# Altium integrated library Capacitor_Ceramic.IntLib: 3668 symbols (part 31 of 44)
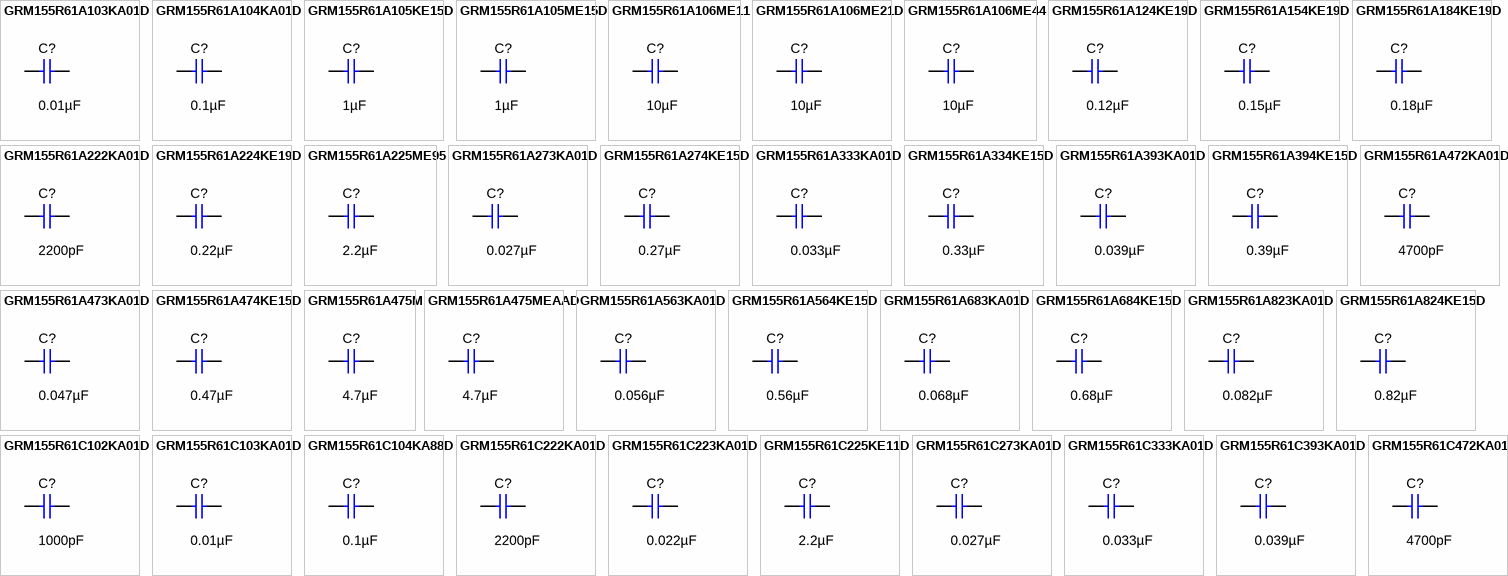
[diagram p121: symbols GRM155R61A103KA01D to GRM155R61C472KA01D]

## GRM155R61A824KE15D
designator C?  ValueDisplayed: 0.82µF  (hidden comment: GRM155R61A824KE15D)
CAP, CERM, 0.82 µF, 10 V,+/- 10%, X5R, 0402; Manufacturer: MuRata; Polarized: N; CompType: Capacitor; Value: 0.82uF; U/M: EA; Cap_F: 0.00000082; Tolerance_%: 10; Value2: 10V; TaMin_C: -55; TaMax_C: 85; Cap_Case: 0402; SizeArea_mm2: 0.5; SizeAreaWB_mm2: 3; SizeX_mm: 1; SizeZ_mm: 0.6; AEC Category: Q200
signal-integrity model Cap
simulation model Cap
footprint 0402
footprint 0402M
footprint 0402L
footprint 0402S
pins: 1, 2

## GRM155R61C102KA01D
designator C?  ValueDisplayed: 1000pF  (hidden comment: GRM155R61C102KA01D)
CAP, CERM, 1000 pF, 16 V,+/- 10%, X5R, 0402; Manufacturer: MuRata; Polarized: N; CompType: Capacitor; Value: 1000pF; U/M: EA; Cap_F: 0.000000001; Tolerance_%: 10; VDC_V: 16; Value2: 16V; TaMin_C: -55; TaMax_C: 85; Cap_Case: 0402; SizeArea_mm2: 0.5; SizeAreaWB_mm2: 3; SizeX_mm: 1; SizeZ_mm: 0.6; AEC Category: Q200
signal-integrity model Cap
simulation model Cap
footprint 0402
footprint 0402M
footprint 0402L
footprint 0402S
pins: 1, 2

## GRM155R61C103KA01D
designator C?  ValueDisplayed: 0.01µF  (hidden comment: GRM155R61C103KA01D)
CAP, CERM, 0.01 µF, 16 V,+/- 10%, X5R, 0402; Manufacturer: MuRata; Polarized: N; CompType: Capacitor; Value: 0.01uF; U/M: EA; Cap_F: 0.00000001; Tolerance_%: 10; VDC_V: 16; Value2: 16V; TaMin_C: -55; TaMax_C: 85; Cap_Case: 0402; SizeArea_mm2: 0.5; SizeAreaWB_mm2: 3; SizeX_mm: 1; SizeZ_mm: 0.6; AEC Category: Q200
signal-integrity model Cap
simulation model Cap
footprint 0402
footprint 0402M
footprint 0402L
footprint 0402S
pins: 1, 2

## GRM155R61C104KA88D
designator C?  ValueDisplayed: 0.1µF  (hidden comment: GRM155R61C104KA88D)
CAP, CERM, 0.1 µF, 16 V,+/- 10%, X5R, 0402; Manufacturer: MuRata; Polarized: N; CompType: Capacitor; Value: 0.1uF; U/M: EA; Cap_F: 0.0000001; Tolerance_%: 10; VDC_V: 16; Value2: 16V; TaMin_C: -55; TaMax_C: 85; Cap_Case: 0402; SizeArea_mm2: 0.5; SizeAreaWB_mm2: 3; SizeX_mm: 1; SizeZ_mm: 0.6; AEC Category: Q200; Green_Lifecycle: Active; Green_REACh: Passed
signal-integrity model Cap
simulation model Cap
footprint 0402
footprint 0402M
footprint 0402L
footprint 0402S
pins: 1, 2

## GRM155R61C222KA01D
designator C?  ValueDisplayed: 2200pF  (hidden comment: GRM155R61C222KA01D)
CAP, CERM, 2200 pF, 16 V,+/- 10%, X5R, 0402; Manufacturer: MuRata; Polarized: N; CompType: Capacitor; Value: 2200pF; U/M: EA; Cap_F: 0.0000000022; Tolerance_%: 10; VDC_V: 16; Value2: 16V; TaMin_C: -55; TaMax_C: 85; Cap_Case: 0402; SizeArea_mm2: 0.5; SizeAreaWB_mm2: 3; SizeX_mm: 1; SizeZ_mm: 0.6; AEC Category: Q200
signal-integrity model Cap
simulation model Cap
footprint 0402
footprint 0402M
footprint 0402L
footprint 0402S
pins: 1, 2

## GRM155R61C223KA01D
designator C?  ValueDisplayed: 0.022µF  (hidden comment: GRM155R61C223KA01D)
CAP, CERM, 0.022 µF, 16 V,+/- 10%, X5R, 0402; Manufacturer: MuRata; Polarized: N; CompType: Capacitor; Value: 0.022uF; U/M: EA; Cap_F: 0.000000022; Tolerance_%: 10; VDC_V: 16; Value2: 16V; TaMin_C: -55; TaMax_C: 85; Cap_Case: 0402; SizeArea_mm2: 0.5; SizeAreaWB_mm2: 3; SizeX_mm: 1; SizeZ_mm: 0.6; AEC Category: Q200; Green_Lifecycle: Active; Green_REACh: Passed
signal-integrity model Cap
simulation model Cap
footprint 0402
footprint 0402M
footprint 0402L
footprint 0402S
pins: 1, 2

## GRM155R61C225KE11D
designator C?  ValueDisplayed: 2.2µF  (hidden comment: GRM155R61C225KE11D)
CAP, CERM, 2.2 µF, 16 V,+/- 10%, X5R, 0402; Manufacturer: MuRata; Polarized: N; CompType: Capacitor; Value: 2.2uF; U/M: EA; Cap_F: 0.0000022; Tolerance_%: 10; VDC_V: 16; Value2: 16V; TaMin_C: -55; TaMax_C: 85; Cap_Case: 0402; SizeArea_mm2: 0.5; SizeAreaWB_mm2: 3; SizeX_mm: 1; SizeZ_mm: 0.6; AEC Category: Q200; Green_Lifecycle: Active; Green_REACh: Passed
signal-integrity model Cap
simulation model Cap
footprint 0402
footprint 0402M
footprint 0402L
footprint 0402S
pins: 1, 2

## GRM155R61C273KA01D
designator C?  ValueDisplayed: 0.027µF  (hidden comment: GRM155R61C273KA01D)
CAP, CERM, 0.027 µF, 16 V,+/- 10%, X5R, 0402; Manufacturer: MuRata; Polarized: N; CompType: Capacitor; Value: 0.027uF; U/M: EA; Cap_F: 0.000000027; Tolerance_%: 10; VDC_V: 16; Value2: 16V; TaMin_C: -55; TaMax_C: 85; Cap_Case: 0402; SizeArea_mm2: 0.5; SizeAreaWB_mm2: 3; SizeX_mm: 1; SizeZ_mm: 0.6; AEC Category: Q200
signal-integrity model Cap
simulation model Cap
footprint 0402
footprint 0402M
footprint 0402L
footprint 0402S
pins: 1, 2

## GRM155R61C333KA01D
designator C?  ValueDisplayed: 0.033µF  (hidden comment: GRM155R61C333KA01D)
CAP, CERM, 0.033 µF, 16 V,+/- 10%, X5R, 0402; Manufacturer: MuRata; Polarized: N; CompType: Capacitor; Value: 0.033uF; U/M: EA; Cap_F: 0.000000033; Tolerance_%: 10; VDC_V: 16; Value2: 16V; TaMin_C: -55; TaMax_C: 85; Cap_Case: 0402; SizeArea_mm2: 0.5; SizeAreaWB_mm2: 3; SizeX_mm: 1; SizeZ_mm: 0.6; AEC Category: Q200; Green_Lifecycle: Active; Green_REACh: Passed
signal-integrity model Cap
simulation model Cap
footprint 0402
footprint 0402M
footprint 0402L
footprint 0402S
pins: 1, 2

## GRM155R61C393KA01D
designator C?  ValueDisplayed: 0.039µF  (hidden comment: GRM155R61C393KA01D)
CAP, CERM, 0.039 µF, 16 V,+/- 10%, X5R, 0402; Manufacturer: MuRata; Polarized: N; CompType: Capacitor; Value: 0.039uF; U/M: EA; Cap_F: 0.000000039; Tolerance_%: 10; VDC_V: 16; Value2: 16V; TaMin_C: -55; TaMax_C: 85; Cap_Case: 0402; SizeArea_mm2: 0.5; SizeAreaWB_mm2: 3; SizeX_mm: 1; SizeZ_mm: 0.6; AEC Category: Q200
signal-integrity model Cap
simulation model Cap
footprint 0402
footprint 0402M
footprint 0402L
footprint 0402S
pins: 1, 2

## GRM155R61C472KA01D
designator C?  ValueDisplayed: 4700pF  (hidden comment: GRM155R61C472KA01D)
CAP, CERM, 4700 pF, 16 V,+/- 10%, X5R, 0402; Manufacturer: MuRata; Polarized: N; CompType: Capacitor; Value: 4700pF; U/M: EA; Cap_F: 0.0000000047; Tolerance_%: 10; VDC_V: 16; Value2: 16V; TaMin_C: -55; TaMax_C: 85; Cap_Case: 0402; SizeArea_mm2: 0.5; SizeAreaWB_mm2: 3; SizeX_mm: 1; SizeZ_mm: 0.6; AEC Category: Q200
signal-integrity model Cap
simulation model Cap
footprint 0402
footprint 0402M
footprint 0402L
footprint 0402S
pins: 1, 2

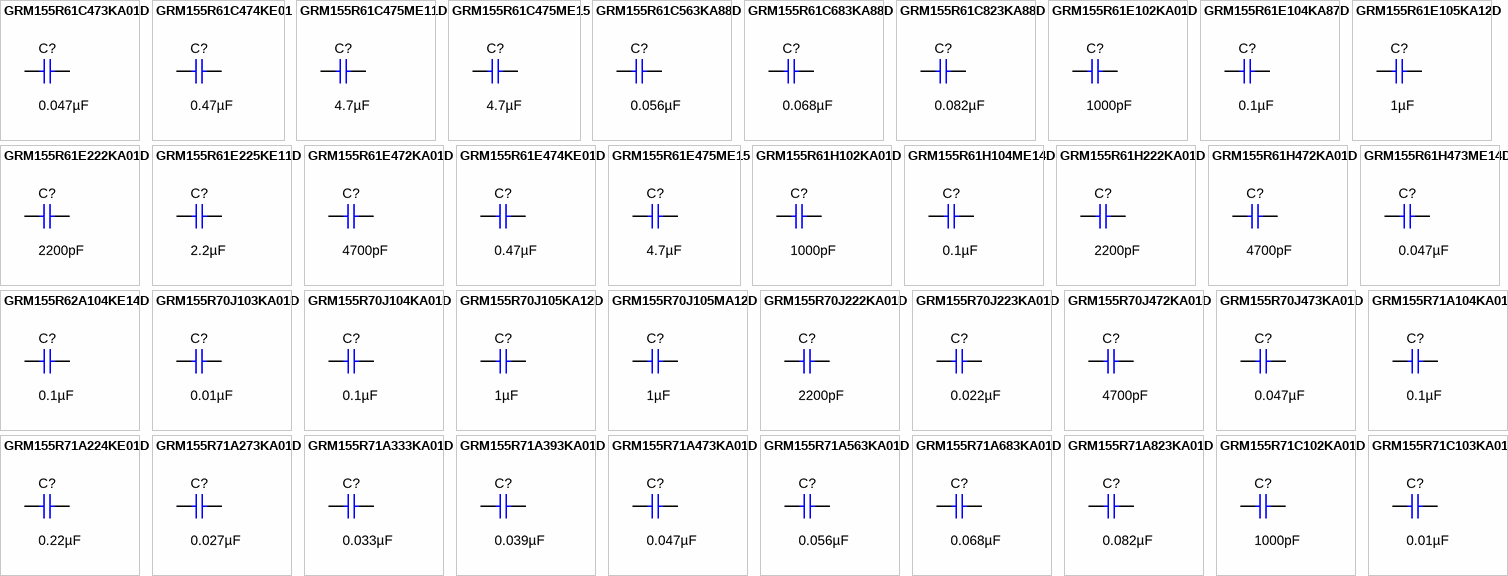
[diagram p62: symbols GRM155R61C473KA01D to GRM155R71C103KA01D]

## GRM155R61C473KA01D
designator C?  ValueDisplayed: 0.047µF  (hidden comment: GRM155R61C473KA01D)
CAP, CERM, 0.047 µF, 16 V,+/- 10%, X5R, 0402; Manufacturer: MuRata; Polarized: N; CompType: Capacitor; Value: 0.047uF; U/M: EA; Cap_F: 0.000000047; Tolerance_%: 10; VDC_V: 16; Value2: 16V; TaMin_C: -55; TaMax_C: 85; Cap_Case: 0402; SizeArea_mm2: 0.5; SizeAreaWB_mm2: 3; SizeX_mm: 1; SizeZ_mm: 0.6; AEC Category: Q200
signal-integrity model Cap
simulation model Cap
footprint 0402
footprint 0402M
footprint 0402L
footprint 0402S
pins: 1, 2

## GRM155R61C474KE01
designator C?  ValueDisplayed: 0.47µF  (hidden comment: GRM155R61C474KE01)
CAP, CERM, 0.47 µF, 16 V,+/- 10%, X5R, 0402; Manufacturer: MuRata; Polarized: N; CompType: Capacitor; Value: 0.47uF; U/M: EA; Cap_F: 0.00000047; Tolerance_%: 10; VDC_V: 16; Value2: 16V; TaMin_C: -55; TaMax_C: 85; Cap_Case: 0402; SizeArea_mm2: 0.5; SizeAreaWB_mm2: 3; SizeX_mm: 1; SizeZ_mm: 0.6; AEC Category: Q200; Green_Lifecycle: Active; Green_REACh: Passed
signal-integrity model Cap
simulation model Cap
footprint 0402
footprint 0402M
footprint 0402L
footprint 0402S
pins: 1, 2

## GRM155R61C475ME11D
designator C?  ValueDisplayed: 4.7µF  (hidden comment: GRM155R61C475ME11D)
CAP, CERM, 4.7 µF, 16 V,+/- 20%, X5R, 0402; Manufacturer: MuRata; Polarized: N; CompType: Capacitor; Value: 4.7uF; U/M: EA; Cap_F: 0.0000047; Tolerance_%: 20; VDC_V: 16; Value2: 16V; TaMin_C: -55; TaMax_C: 85; Cap_Case: 0402; SizeArea_mm2: 0.5; SizeAreaWB_mm2: 3; SizeX_mm: 1; SizeZ_mm: 0.6; AEC Category: Q200; Green_Lifecycle: Not Set; Green_REACh: Incomplete
signal-integrity model Cap
simulation model Cap
footprint 0402
footprint 0402M
footprint 0402L
footprint 0402S
pins: 1, 2

## GRM155R61C475ME15
designator C?  ValueDisplayed: 4.7µF  (hidden comment: GRM155R61C475ME15)
CAP, CERM, 4.7 µF, 16 V,+/- 20%, X5R, 0402; Manufacturer: MuRata; Polarized: N; CompType: Capacitor; Value: 4.7uF; U/M: EA; Cap_F: 0.0000047; Tolerance_%: 20; VDC_V: 16; Value2: 16V; TaMin_C: -55; TaMax_C: 85; Cap_Case: 0402; SizeArea_mm2: 0.5; SizeAreaWB_mm2: 3; SizeX_mm: 1; SizeZ_mm: 0.6; AEC Category: Q200; Green_Lifecycle: Not Set; Green_REACh: Incomplete
signal-integrity model Cap
simulation model Cap
footprint 0402
footprint 0402M
footprint 0402L
footprint 0402S
pins: 1, 2

## GRM155R61C563KA88D
designator C?  ValueDisplayed: 0.056µF  (hidden comment: GRM155R61C563KA88D)
CAP, CERM, 0.056 µF, 16 V,+/- 10%, X5R, 0402; Manufacturer: MuRata; Polarized: N; CompType: Capacitor; Value: 0.056uF; U/M: EA; Cap_F: 0.000000056; Tolerance_%: 10; VDC_V: 16; Value2: 16V; TaMin_C: -55; TaMax_C: 85; Cap_Case: 0402; SizeArea_mm2: 0.5; SizeAreaWB_mm2: 3; SizeX_mm: 1; SizeZ_mm: 0.6; AEC Category: Q200
signal-integrity model Cap
simulation model Cap
footprint 0402
footprint 0402M
footprint 0402L
footprint 0402S
pins: 1, 2

## GRM155R61C683KA88D
designator C?  ValueDisplayed: 0.068µF  (hidden comment: GRM155R61C683KA88D)
CAP, CERM, 0.068 µF, 16 V,+/- 10%, X5R, 0402; Manufacturer: MuRata; Polarized: N; CompType: Capacitor; Value: 0.068uF; U/M: EA; Cap_F: 0.000000068; Tolerance_%: 10; VDC_V: 16; Value2: 16V; TaMin_C: -55; TaMax_C: 85; Cap_Case: 0402; SizeArea_mm2: 0.5; SizeAreaWB_mm2: 3; SizeX_mm: 1; SizeZ_mm: 0.6; AEC Category: Q200
signal-integrity model Cap
simulation model Cap
footprint 0402
footprint 0402M
footprint 0402L
footprint 0402S
pins: 1, 2

## GRM155R61C823KA88D
designator C?  ValueDisplayed: 0.082µF  (hidden comment: GRM155R61C823KA88D)
CAP, CERM, 0.082 µF, 16 V,+/- 10%, X5R, 0402; Manufacturer: MuRata; Polarized: N; CompType: Capacitor; Value: 0.082uF; U/M: EA; Cap_F: 0.000000082; Tolerance_%: 10; VDC_V: 16; Value2: 16V; TaMin_C: -55; TaMax_C: 85; Cap_Case: 0402; SizeArea_mm2: 0.5; SizeAreaWB_mm2: 3; SizeX_mm: 1; SizeZ_mm: 0.6; AEC Category: Q200
signal-integrity model Cap
simulation model Cap
footprint 0402
footprint 0402M
footprint 0402L
footprint 0402S
pins: 1, 2

## GRM155R61E102KA01D
designator C?  ValueDisplayed: 1000pF  (hidden comment: GRM155R61E102KA01D)
CAP, CERM, 1000 pF, 25 V,+/- 10%, X5R, 0402; Manufacturer: MuRata; Polarized: N; CompType: Capacitor; Value: 1000pF; U/M: EA; Cap_F: 0.000000001; Tolerance_%: 10; VDC_V: 25; Value2: 25V; TaMin_C: -55; TaMax_C: 85; Cap_Case: 0402; SizeArea_mm2: 0.5; SizeAreaWB_mm2: 3; SizeX_mm: 1; SizeZ_mm: 0.6; AEC Category: Q200
signal-integrity model Cap
simulation model Cap
footprint 0402
footprint 0402M
footprint 0402L
footprint 0402S
pins: 1, 2

## GRM155R61E104KA87D
designator C?  ValueDisplayed: 0.1µF  (hidden comment: GRM155R61E104KA87D)
CAP, CERM, 0.1 µF, 25 V,+/- 10%, X5R, 0402; Manufacturer: MuRata; Polarized: N; CompType: Capacitor; Value: 0.1uF; U/M: EA; Cap_F: 0.0000001; Tolerance_%: 10; VDC_V: 25; Value2: 25V; TaMin_C: -55; TaMax_C: 85; Cap_Case: 0402; SizeArea_mm2: 0.5; SizeAreaWB_mm2: 3; SizeX_mm: 1; SizeZ_mm: 0.6; AEC Category: Q200; Green_Lifecycle: Active; Green_REACh: Passed
signal-integrity model Cap
simulation model Cap
footprint 0402
footprint 0402M
footprint 0402L
footprint 0402S
pins: 1, 2

## GRM155R61E105KA12D
designator C?  ValueDisplayed: 1µF  (hidden comment: GRM155R61E105KA12D)
CAP, CERM, 1 µF, 25 V,+/- 10%, X5R, 0402; Manufacturer: MuRata; Polarized: N; CompType: Capacitor; Value: 1uF; U/M: EA; Cap_F: 0.000001; Tolerance_%: 10; VDC_V: 25; Value2: 25V; TaMin_C: -55; TaMax_C: 85; Cap_Case: 0402; SizeArea_mm2: 0.5; SizeAreaWB_mm2: 3; SizeX_mm: 1; SizeZ_mm: 0.6; AEC Category: Q200
signal-integrity model Cap
simulation model Cap
footprint 0402
footprint 0402M
footprint 0402L
footprint 0402S
pins: 1, 2

## GRM155R61E222KA01D
designator C?  ValueDisplayed: 2200pF  (hidden comment: GRM155R61E222KA01D)
CAP, CERM, 2200 pF, 25 V,+/- 10%, X5R, 0402; Manufacturer: MuRata; Polarized: N; CompType: Capacitor; Value: 2200pF; U/M: EA; Cap_F: 0.0000000022; Tolerance_%: 10; VDC_V: 25; Value2: 25V; TaMin_C: -55; TaMax_C: 85; Cap_Case: 0402; SizeArea_mm2: 0.5; SizeAreaWB_mm2: 3; SizeX_mm: 1; SizeZ_mm: 0.6; AEC Category: Q200; Green_Lifecycle: Active; Green_REACh: Passed
signal-integrity model Cap
simulation model Cap
footprint 0402
footprint 0402M
footprint 0402L
footprint 0402S
pins: 1, 2

## GRM155R61E225KE11D
designator C?  ValueDisplayed: 2.2µF  (hidden comment: GRM155R61E225KE11D)
CAP, CERM, 2.2 µF, 25 V,+/- 10%, X5R, 0402; Manufacturer: MuRata; Polarized: N; CompType: Capacitor; Value: 2.2uF; U/M: EA; Cap_F: 0.0000022; Tolerance_%: 10; VDC_V: 25; Value2: 25V; TaMin_C: -55; TaMax_C: 85; Cap_Case: 0402; SizeArea_mm2: 0.5; SizeAreaWB_mm2: 3; SizeX_mm: 1; SizeZ_mm: 0.7; AEC Category: Q200; Green_Lifecycle: Active; Green_REACh: Passed
signal-integrity model Cap
simulation model Cap
footprint 0402_070
pins: 1, 2

## GRM155R61E472KA01D
designator C?  ValueDisplayed: 4700pF  (hidden comment: GRM155R61E472KA01D)
CAP, CERM, 4700 pF, 25 V,+/- 10%, X5R, 0402; Manufacturer: MuRata; Polarized: N; CompType: Capacitor; Value: 4700pF; U/M: EA; Cap_F: 0.0000000047; Tolerance_%: 10; VDC_V: 25; Value2: 25V; TaMin_C: -55; TaMax_C: 85; Cap_Case: 0402; SizeArea_mm2: 0.5; SizeAreaWB_mm2: 3; SizeX_mm: 1; SizeZ_mm: 0.6; AEC Category: Q200
signal-integrity model Cap
simulation model Cap
footprint 0402
footprint 0402M
footprint 0402L
footprint 0402S
pins: 1, 2

## GRM155R61E474KE01D
designator C?  ValueDisplayed: 0.47µF  (hidden comment: GRM155R61E474KE01D)
CAP, CERM, 0.47 µF, 25 V,+/- 10%, X5R, 0402; Manufacturer: MuRata; Polarized: N; CompType: Capacitor; Value: 0.47uF; U/M: EA; Cap_F: 0.00000047; Tolerance_%: 10; VDC_V: 25; Value2: 25V; TaMin_C: -55; TaMax_C: 85; Cap_Case: 0402; SizeArea_mm2: 0.5; SizeAreaWB_mm2: 3; SizeX_mm: 1; SizeZ_mm: 0.6; AEC Category: Q200
signal-integrity model Cap
simulation model Cap
footprint 0402
footprint 0402M
footprint 0402L
footprint 0402S
pins: 1, 2

## GRM155R61E475ME15
designator C?  ValueDisplayed: 4.7µF  (hidden comment: GRM155R61E475ME15)
CAP, CERM, 4.7 µF, 25 V,+/- 20%, X5R, 0402; Manufacturer: MuRata; Polarized: N; CompType: Capacitor; Value: 4.7uF; U/M: EA; Cap_F: 0.0000047; Tolerance_%: 20; VDC_V: 25; Value2: 25V; TaMin_C: -55; TaMax_C: 85; Cap_Case: 0402; SizeArea_mm2: 0.5; SizeAreaWB_mm2: 3; SizeX_mm: 1; SizeZ_mm: 0.6; AEC Category: Q200
signal-integrity model Cap
simulation model Cap
footprint 0402
footprint 0402M
footprint 0402L
footprint 0402S
pins: 1, 2

## GRM155R61H102KA01D
designator C?  ValueDisplayed: 1000pF  (hidden comment: GRM155R61H102KA01D)
CAP, CERM, 1000 pF, 50 V,+/- 10%, X5R, 0402; Manufacturer: MuRata; Polarized: N; CompType: Capacitor; Value: 1000pF; U/M: EA; Cap_F: 0.000000001; Tolerance_%: 10; VDC_V: 50; Value2: 50V; TaMin_C: -55; TaMax_C: 85; Cap_Case: 0402; SizeArea_mm2: 0.5; SizeAreaWB_mm2: 3; SizeX_mm: 1; SizeZ_mm: 0.6; AEC Category: Q200
signal-integrity model Cap
simulation model Cap
footprint 0402
footprint 0402M
footprint 0402L
footprint 0402S
pins: 1, 2

## GRM155R61H104ME14D
designator C?  ValueDisplayed: 0.1µF  (hidden comment: GRM155R61H104ME14D)
CAP, CERM, 0.1 µF, 50 V,+/- 20%, X5R, 0402; Manufacturer: MuRata; Polarized: N; CompType: Capacitor; Value: 0.1uF; U/M: EA; Cap_F: 0.0000001; Tolerance_%: 20; VDC_V: 50; Value2: 50V; TaMin_C: -55; TaMax_C: 85; Cap_Case: 0402; SizeArea_mm2: 0.5; SizeAreaWB_mm2: 3; SizeX_mm: 1; SizeZ_mm: 0.6; AEC Category: Q200
signal-integrity model Cap
simulation model Cap
footprint 0402
footprint 0402M
footprint 0402L
footprint 0402S
pins: 1, 2

## GRM155R61H222KA01D
designator C?  ValueDisplayed: 2200pF  (hidden comment: GRM155R61H222KA01D)
CAP, CERM, 2200 pF, 50 V,+/- 10%, X5R, 0402; Manufacturer: MuRata; Polarized: N; CompType: Capacitor; Value: 2200pF; U/M: EA; Cap_F: 0.0000000022; Tolerance_%: 10; VDC_V: 50; Value2: 50V; TaMin_C: -55; TaMax_C: 85; Cap_Case: 0402; SizeArea_mm2: 0.5; SizeAreaWB_mm2: 3; SizeX_mm: 1; SizeZ_mm: 0.6; AEC Category: Q200; Green_Lifecycle: Active; Green_REACh: Passed
signal-integrity model Cap
simulation model Cap
footprint 0402
footprint 0402M
footprint 0402L
footprint 0402S
pins: 1, 2

## GRM155R61H472KA01D
designator C?  ValueDisplayed: 4700pF  (hidden comment: GRM155R61H472KA01D)
CAP, CERM, 4700 pF, 50 V,+/- 10%, X5R, 0402; Manufacturer: MuRata; Polarized: N; CompType: Capacitor; Value: 4700pF; U/M: EA; Cap_F: 0.0000000047; Tolerance_%: 10; VDC_V: 50; Value2: 50V; TaMin_C: -55; TaMax_C: 85; Cap_Case: 0402; SizeArea_mm2: 0.5; SizeAreaWB_mm2: 3; SizeX_mm: 1; SizeZ_mm: 0.6; AEC Category: Q200; Green_Lifecycle: Active; Green_REACh: Passed
signal-integrity model Cap
simulation model Cap
footprint 0402
footprint 0402M
footprint 0402L
footprint 0402S
pins: 1, 2

## GRM155R61H473ME14D
designator C?  ValueDisplayed: 0.047µF  (hidden comment: GRM155R61H473ME14D)
CAP, CERM, 0.047 µF, 50 V,+/- 20%, X5R, 0402; Manufacturer: MuRata; Polarized: N; CompType: Capacitor; Value: 0.047uF; U/M: EA; Cap_F: 0.000000047; Tolerance_%: 20; VDC_V: 50; Value2: 50V; TaMin_C: -55; TaMax_C: 85; Cap_Case: 0402; SizeArea_mm2: 0.5; SizeAreaWB_mm2: 3; SizeX_mm: 1; SizeZ_mm: 0.6; AEC Category: Q200
signal-integrity model Cap
simulation model Cap
footprint 0402
footprint 0402M
footprint 0402L
footprint 0402S
pins: 1, 2

## GRM155R62A104KE14D
designator C?  ValueDisplayed: 0.1µF  (hidden comment: GRM155R62A104KE14D)
CAP, CERM, 0.1 µF, 100 V,+/- 10%, X5R, 0402; Manufacturer: MuRata; Polarized: N; CompType: Capacitor; Value: 0.1uF; U/M: EA; Cap_F: 0.0000001; Tolerance_%: 10; VDC_V: 100; Value2: 100V; TaMin_C: -55; TaMax_C: 85; Cap_Case: 0402; SizeArea_mm2: 0.5; SizeAreaWB_mm2: 3; SizeX_mm: 1; SizeZ_mm: 0.6; AEC Category: Q200
signal-integrity model Cap
simulation model Cap
footprint 0402
footprint 0402M
footprint 0402L
footprint 0402S
pins: 1, 2

## GRM155R70J103KA01D
designator C?  ValueDisplayed: 0.01µF  (hidden comment: GRM155R70J103KA01D)
CAP, CERM, 0.01 µF, 6.3 V,+/- 10%, X7R, 0402; Manufacturer: MuRata; Polarized: N; CompType: Capacitor; Value: 0.01uF; U/M: EA; Cap_F: 0.00000001; Tolerance_%: 10; VDC_V: 6.3; Value2: 6.3V; TaMin_C: -55; TaMax_C: 125; Cap_Case: 0402; SizeArea_mm2: 0.5; SizeAreaWB_mm2: 3; SizeX_mm: 1; SizeZ_mm: 0.6; AEC Category: Q200; Green_Lifecycle: Active; Green_REACh: Passed
signal-integrity model Cap
simulation model Cap
footprint 0402
footprint 0402M
footprint 0402L
footprint 0402S
pins: 1, 2

## GRM155R70J104KA01D
designator C?  ValueDisplayed: 0.1µF  (hidden comment: GRM155R70J104KA01D)
CAP, CERM, 0.1 µF, 6.3 V,+/- 10%, X7R, 0402; Manufacturer: MuRata; Polarized: N; CompType: Capacitor; Value: 0.1uF; U/M: EA; Cap_F: 0.0000001; Tolerance_%: 10; VDC_V: 6.3; Value2: 6.3V; TaMin_C: -55; TaMax_C: 125; Cap_Case: 0402; SizeArea_mm2: 0.5; SizeAreaWB_mm2: 3; SizeX_mm: 1; SizeZ_mm: 0.6; AEC Category: Q200; Green_Lifecycle: Active; Green_REACh: Passed
signal-integrity model Cap
simulation model Cap
footprint 0402
footprint 0402M
footprint 0402L
footprint 0402S
pins: 1, 2

## GRM155R70J105KA12D
designator C?  ValueDisplayed: 1µF  (hidden comment: GRM155R70J105KA12D)
CAP, CERM, 1 µF, 6.3 V,+/- 10%, X7R, 0402; Manufacturer: MuRata; Polarized: N; CompType: Capacitor; Value: 1uF; U/M: EA; Cap_F: 0.000001; Tolerance_%: 10; VDC_V: 6.3; Value2: 6.3V; TaMin_C: -55; TaMax_C: 125; Cap_Case: 0402; SizeArea_mm2: 0.5; SizeAreaWB_mm2: 3; SizeX_mm: 1; SizeZ_mm: 0.6; AEC Category: Q200
signal-integrity model Cap
simulation model Cap
footprint 0402
footprint 0402M
footprint 0402L
footprint 0402S
pins: 1, 2

## GRM155R70J105MA12D
designator C?  ValueDisplayed: 1µF  (hidden comment: GRM155R70J105MA12D)
CAP, CERM, 1 µF, 6.3 V,+/- 20%, X7R, 0402; Manufacturer: MuRata; Polarized: N; CompType: Capacitor; Value: 1uF; U/M: EA; Cap_F: 0.000001; Tolerance_%: 20; VDC_V: 6.3; Value2: 6.3V; TaMin_C: -55; TaMax_C: 125; Cap_Case: 0402; SizeArea_mm2: 0.5; SizeAreaWB_mm2: 3; SizeX_mm: 1; SizeZ_mm: 0.6; AEC Category: Q200
signal-integrity model Cap
simulation model Cap
footprint 0402
footprint 0402M
footprint 0402L
footprint 0402S
pins: 1, 2

## GRM155R70J222KA01D
designator C?  ValueDisplayed: 2200pF  (hidden comment: GRM155R70J222KA01D)
CAP, CERM, 2200 pF, 6.3 V,+/- 10%, X7R, 0402; Manufacturer: MuRata; Polarized: N; CompType: Capacitor; Value: 2200pF; U/M: EA; Cap_F: 0.0000000022; Tolerance_%: 10; VDC_V: 6.3; Value2: 6.3V; TaMin_C: -55; TaMax_C: 125; Cap_Case: 0402; SizeArea_mm2: 0.5; SizeAreaWB_mm2: 3; SizeX_mm: 1; SizeZ_mm: 0.6; AEC Category: Q200
signal-integrity model Cap
simulation model Cap
footprint 0402
footprint 0402M
footprint 0402L
footprint 0402S
pins: 1, 2

## GRM155R70J223KA01D
designator C?  ValueDisplayed: 0.022µF  (hidden comment: GRM155R70J223KA01D)
CAP, CERM, 0.022 µF, 6.3 V,+/- 10%, X7R, 0402; Manufacturer: MuRata; Polarized: N; CompType: Capacitor; Value: 0.022uF; U/M: EA; Cap_F: 0.000000022; Tolerance_%: 10; VDC_V: 6.3; Value2: 6.3V; TaMin_C: -55; TaMax_C: 125; Cap_Case: 0402; SizeArea_mm2: 0.5; SizeAreaWB_mm2: 3; SizeX_mm: 1; SizeZ_mm: 0.6; AEC Category: Q200
signal-integrity model Cap
simulation model Cap
footprint 0402
footprint 0402M
footprint 0402L
footprint 0402S
pins: 1, 2

## GRM155R70J472KA01D
designator C?  ValueDisplayed: 4700pF  (hidden comment: GRM155R70J472KA01D)
CAP, CERM, 4700 pF, 6.3 V,+/- 10%, X7R, 0402; Manufacturer: MuRata; Polarized: N; CompType: Capacitor; Value: 4700pF; U/M: EA; Cap_F: 0.0000000047; Tolerance_%: 10; VDC_V: 6.3; Value2: 6.3V; TaMin_C: -55; TaMax_C: 125; Cap_Case: 0402; SizeArea_mm2: 0.5; SizeAreaWB_mm2: 3; SizeX_mm: 1; SizeZ_mm: 0.6; AEC Category: Q200
signal-integrity model Cap
simulation model Cap
footprint 0402
footprint 0402M
footprint 0402L
footprint 0402S
pins: 1, 2

## GRM155R70J473KA01D
designator C?  ValueDisplayed: 0.047µF  (hidden comment: GRM155R70J473KA01D)
CAP, CERM, 0.047 µF, 6.3 V,+/- 10%, X7R, 0402; Manufacturer: MuRata; Polarized: N; CompType: Capacitor; Value: 0.047uF; U/M: EA; Cap_F: 0.000000047; Tolerance_%: 10; VDC_V: 6.3; Value2: 6.3V; TaMin_C: -55; TaMax_C: 125; Cap_Case: 0402; SizeArea_mm2: 0.5; SizeAreaWB_mm2: 3; SizeX_mm: 1; SizeZ_mm: 0.6; AEC Category: Q200
signal-integrity model Cap
simulation model Cap
footprint 0402
footprint 0402M
footprint 0402L
footprint 0402S
pins: 1, 2

## GRM155R71A104KA01D
designator C?  ValueDisplayed: 0.1µF  (hidden comment: GRM155R71A104KA01D)
CAP, CERM, 0.1 µF, 10 V,+/- 10%, X7R, 0402; Manufacturer: MuRata; Polarized: N; CompType: Capacitor; Value: 0.1uF; U/M: EA; Cap_F: 0.0000001; Tolerance_%: 10; Value2: 10V; TaMin_C: -55; TaMax_C: 125; Cap_Case: 0402; SizeArea_mm2: 0.5; SizeAreaWB_mm2: 3; SizeX_mm: 1; SizeZ_mm: 0.6; AEC Category: Q200; Green_Lifecycle: Active; Green_REACh: Passed
signal-integrity model Cap
simulation model Cap
footprint 0402
footprint 0402M
footprint 0402L
footprint 0402S
pins: 1, 2

## GRM155R71A224KE01D
designator C?  ValueDisplayed: 0.22µF  (hidden comment: GRM155R71A224KE01D)
CAP, CERM, 0.22 µF, 10 V,+/- 10%, X7R, 0402; Manufacturer: MuRata; Polarized: N; CompType: Capacitor; Value: 0.22uF; U/M: EA; Cap_F: 0.00000022; Tolerance_%: 10; Value2: 10V; TaMin_C: -55; TaMax_C: 125; Cap_Case: 0402; SizeArea_mm2: 0.5; SizeAreaWB_mm2: 3; SizeX_mm: 1; SizeZ_mm: 0.6; AEC Category: Q200
signal-integrity model Cap
simulation model Cap
footprint 0402
footprint 0402M
footprint 0402L
footprint 0402S
pins: 1, 2

## GRM155R71A273KA01D
designator C?  ValueDisplayed: 0.027µF  (hidden comment: GRM155R71A273KA01D)
CAP, CERM, 0.027 µF, 10 V,+/- 10%, X7R, 0402; Manufacturer: MuRata; Polarized: N; CompType: Capacitor; Value: 0.027uF; U/M: EA; Cap_F: 0.000000027; Tolerance_%: 10; Value2: 10V; TaMin_C: -55; TaMax_C: 125; Cap_Case: 0402; SizeArea_mm2: 0.5; SizeAreaWB_mm2: 3; SizeX_mm: 1; SizeZ_mm: 0.6; AEC Category: Q200
signal-integrity model Cap
simulation model Cap
footprint 0402
footprint 0402M
footprint 0402L
footprint 0402S
pins: 1, 2

## GRM155R71A333KA01D
designator C?  ValueDisplayed: 0.033µF  (hidden comment: GRM155R71A333KA01D)
CAP, CERM, 0.033 µF, 10 V,+/- 10%, X7R, 0402; Manufacturer: MuRata; Polarized: N; CompType: Capacitor; Value: 0.033uF; U/M: EA; Cap_F: 0.000000033; Tolerance_%: 10; Value2: 10V; TaMin_C: -55; TaMax_C: 125; Cap_Case: 0402; SizeArea_mm2: 0.5; SizeAreaWB_mm2: 3; SizeX_mm: 1; SizeZ_mm: 0.6; AEC Category: Q200; Green_Lifecycle: Active; Green_REACh: Passed
signal-integrity model Cap
simulation model Cap
footprint 0402
footprint 0402M
footprint 0402L
footprint 0402S
pins: 1, 2

## GRM155R71A393KA01D
designator C?  ValueDisplayed: 0.039µF  (hidden comment: GRM155R71A393KA01D)
CAP, CERM, 0.039 µF, 10 V,+/- 10%, X7R, 0402; Manufacturer: MuRata; Polarized: N; CompType: Capacitor; Value: 0.039uF; U/M: EA; Cap_F: 0.000000039; Tolerance_%: 10; Value2: 10V; TaMin_C: -55; TaMax_C: 125; Cap_Case: 0402; SizeArea_mm2: 0.5; SizeAreaWB_mm2: 3; SizeX_mm: 1; SizeZ_mm: 0.6; AEC Category: Q200
signal-integrity model Cap
simulation model Cap
footprint 0402
footprint 0402M
footprint 0402L
footprint 0402S
pins: 1, 2

## GRM155R71A473KA01D
designator C?  ValueDisplayed: 0.047µF  (hidden comment: GRM155R71A473KA01D)
CAP, CERM, 0.047 µF, 10 V,+/- 10%, X7R, 0402; Manufacturer: MuRata; Polarized: N; CompType: Capacitor; Value: 0.047uF; U/M: EA; Cap_F: 0.000000047; Tolerance_%: 10; Value2: 10V; TaMin_C: -55; TaMax_C: 125; Cap_Case: 0402; SizeArea_mm2: 0.5; SizeAreaWB_mm2: 3; SizeX_mm: 1; SizeZ_mm: 0.6; AEC Category: Q200; Green_Lifecycle: Active; Green_REACh: Passed
signal-integrity model Cap
simulation model Cap
footprint 0402
footprint 0402M
footprint 0402L
footprint 0402S
pins: 1, 2

## GRM155R71A563KA01D
designator C?  ValueDisplayed: 0.056µF  (hidden comment: GRM155R71A563KA01D)
CAP, CERM, 0.056 µF, 10 V,+/- 10%, X7R, 0402; Manufacturer: MuRata; Polarized: N; CompType: Capacitor; Value: 0.056uF; U/M: EA; Cap_F: 0.000000056; Tolerance_%: 10; Value2: 10V; TaMin_C: -55; TaMax_C: 125; Cap_Case: 0402; SizeArea_mm2: 0.5; SizeAreaWB_mm2: 3; SizeX_mm: 1; SizeZ_mm: 0.6; AEC Category: Q200
signal-integrity model Cap
simulation model Cap
footprint 0402
footprint 0402M
footprint 0402L
footprint 0402S
pins: 1, 2

## GRM155R71A683KA01D
designator C?  ValueDisplayed: 0.068µF  (hidden comment: GRM155R71A683KA01D)
CAP, CERM, 0.068 µF, 10 V,+/- 10%, X7R, 0402; Manufacturer: MuRata; Polarized: N; CompType: Capacitor; Value: 0.068uF; U/M: EA; Cap_F: 0.000000068; Tolerance_%: 10; Value2: 10V; TaMin_C: -55; TaMax_C: 125; Cap_Case: 0402; SizeArea_mm2: 0.5; SizeAreaWB_mm2: 3; SizeX_mm: 1; SizeZ_mm: 0.6; AEC Category: Q200
signal-integrity model Cap
simulation model Cap
footprint 0402
footprint 0402M
footprint 0402L
footprint 0402S
pins: 1, 2

## GRM155R71A823KA01D
designator C?  ValueDisplayed: 0.082µF  (hidden comment: GRM155R71A823KA01D)
CAP, CERM, 0.082 µF, 10 V,+/- 10%, X7R, 0402; Manufacturer: MuRata; Polarized: N; CompType: Capacitor; Value: 0.082uF; U/M: EA; Cap_F: 0.000000082; Tolerance_%: 10; Value2: 10V; TaMin_C: -55; TaMax_C: 125; Cap_Case: 0402; SizeArea_mm2: 0.5; SizeAreaWB_mm2: 3; SizeX_mm: 1; SizeZ_mm: 0.6; AEC Category: Q200
signal-integrity model Cap
simulation model Cap
footprint 0402
footprint 0402M
footprint 0402L
footprint 0402S
pins: 1, 2

## GRM155R71C102KA01D
designator C?  ValueDisplayed: 1000pF  (hidden comment: GRM155R71C102KA01D)
CAP, CERM, 1000 pF, 16 V,+/- 10%, X7R, 0402; Manufacturer: MuRata; Polarized: N; CompType: Capacitor; Value: 1000pF; U/M: EA; Cap_F: 0.000000001; Tolerance_%: 10; VDC_V: 16; Value2: 16V; TaMin_C: -55; TaMax_C: 125; Cap_Case: 0402; SizeArea_mm2: 0.5; SizeAreaWB_mm2: 3; SizeX_mm: 1; SizeZ_mm: 0.6; AEC Category: Q200; Green_Lifecycle: Active; Green_REACh: Passed
signal-integrity model Cap
simulation model Cap
footprint 0402
footprint 0402M
footprint 0402L
footprint 0402S
pins: 1, 2

## GRM155R71C103KA01D
designator C?  ValueDisplayed: 0.01µF  (hidden comment: GRM155R71C103KA01D)
CAP, CERM, 0.01 µF, 16 V,+/- 10%, X7R, 0402; Manufacturer: MuRata; Polarized: N; CompType: Capacitor; Value: 0.01uF; U/M: EA; Cap_F: 0.00000001; Tolerance_%: 10; VDC_V: 16; Value2: 16V; TaMin_C: -55; TaMax_C: 125; Cap_Case: 0402; SizeArea_mm2: 0.5; SizeAreaWB_mm2: 3; SizeX_mm: 1; SizeZ_mm: 0.6; AEC Category: Q200; Green_Lifecycle: Active; Green_REACh: Passed
signal-integrity model Cap
simulation model Cap
footprint 0402
footprint 0402M
footprint 0402L
footprint 0402S
pins: 1, 2

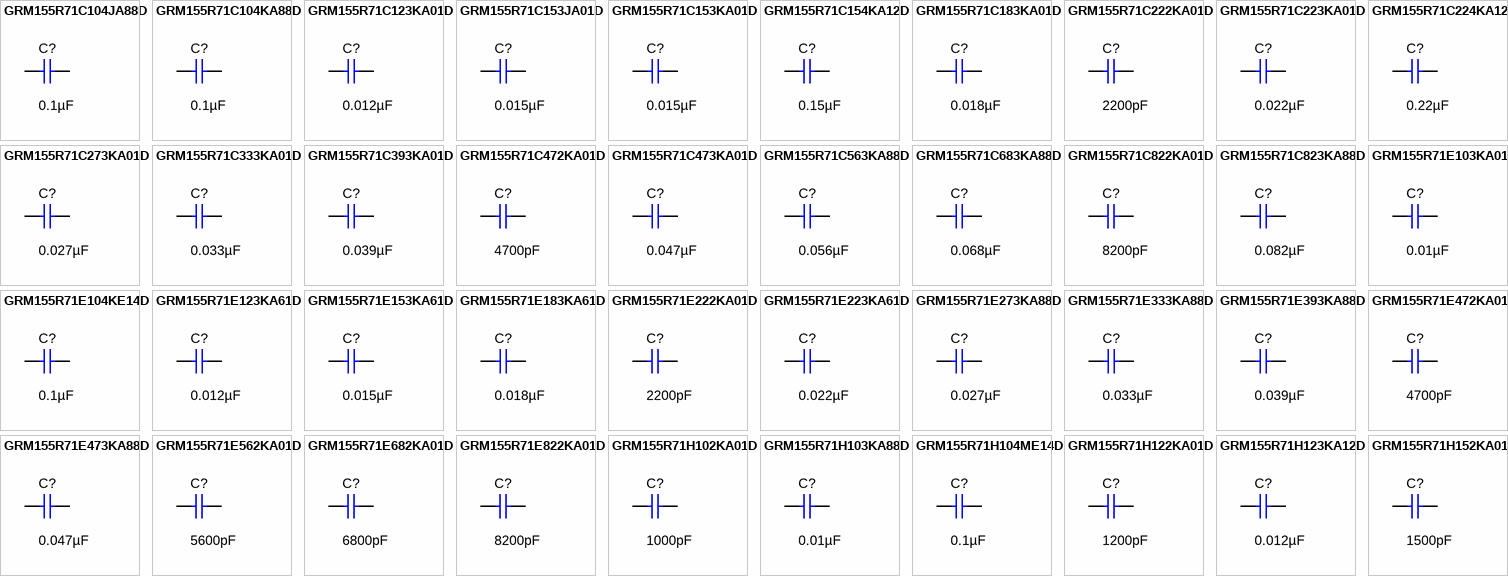
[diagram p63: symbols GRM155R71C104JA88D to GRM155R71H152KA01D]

## GRM155R71C104JA88D
designator C?  ValueDisplayed: 0.1µF  (hidden comment: GRM155R71C104JA88D)
CAP, CERM, 0.1 µF, 16 V,+/- 5%, X7R, 0402; Manufacturer: MuRata; Polarized: N; CompType: Capacitor; Value: 0.1uF; U/M: EA; Cap_F: 0.0000001; Tolerance_%: 5; VDC_V: 16; Value2: 16V; TaMin_C: -55; TaMax_C: 125; Cap_Case: 0402; SizeArea_mm2: 0.5; SizeAreaWB_mm2: 3; SizeX_mm: 1; SizeZ_mm: 0.6; AEC Category: Q200; Green_Lifecycle: Active; Green_REACh: Passed
signal-integrity model Cap
simulation model Cap
footprint 0402
footprint 0402M
footprint 0402L
footprint 0402S
pins: 1, 2

## GRM155R71C104KA88D
designator C?  ValueDisplayed: 0.1µF  (hidden comment: GRM155R71C104KA88D)
CAP, CERM, 0.1 µF, 16 V,+/- 10%, X7R, 0402; Manufacturer: MuRata; Polarized: N; CompType: Capacitor; Value: 0.1uF; U/M: EA; Cap_F: 0.0000001; Tolerance_%: 10; VDC_V: 16; Value2: 16V; TaMin_C: -55; TaMax_C: 125; Cap_Case: 0402; SizeArea_mm2: 0.5; SizeAreaWB_mm2: 3; SizeX_mm: 1; SizeZ_mm: 0.6; AEC Category: Q200; Green_Lifecycle: Active; Green_REACh: Passed
signal-integrity model Cap
simulation model Cap
footprint 0402
footprint 0402M
footprint 0402L
footprint 0402S
pins: 1, 2

## GRM155R71C123KA01D
designator C?  ValueDisplayed: 0.012µF  (hidden comment: GRM155R71C123KA01D)
CAP, CERM, 0.012 µF, 16 V,+/- 10%, X7R, 0402; Manufacturer: MuRata; Polarized: N; CompType: Capacitor; Value: 0.012uF; U/M: EA; Cap_F: 0.000000012; Tolerance_%: 10; VDC_V: 16; Value2: 16V; TaMin_C: -55; TaMax_C: 125; Cap_Case: 0402; SizeArea_mm2: 0.5; SizeAreaWB_mm2: 3; SizeX_mm: 1; SizeZ_mm: 0.6; AEC Category: Q200; Green_Lifecycle: Active; Green_REACh: Passed
signal-integrity model Cap
simulation model Cap
footprint 0402
footprint 0402M
footprint 0402L
footprint 0402S
pins: 1, 2

## GRM155R71C153JA01D
designator C?  ValueDisplayed: 0.015µF  (hidden comment: GRM155R71C153JA01D)
CAP, CERM, 0.015 µF, 16 V,+/- 5%, X7R, 0402; Manufacturer: MuRata; Polarized: N; CompType: Capacitor; Value: 0.015uF; U/M: EA; Cap_F: 0.000000015; Tolerance_%: 5; VDC_V: 16; Value2: 16V; TaMin_C: -55; TaMax_C: 125; Cap_Case: 0402; SizeArea_mm2: 0.5; SizeAreaWB_mm2: 3; SizeX_mm: 1; SizeZ_mm: 0.6; AEC Category: Q200
signal-integrity model Cap
simulation model Cap
footprint 0402
footprint 0402M
footprint 0402L
footprint 0402S
pins: 1, 2

## GRM155R71C153KA01D
designator C?  ValueDisplayed: 0.015µF  (hidden comment: GRM155R71C153KA01D)
CAP, CERM, 0.015 µF, 16 V,+/- 10%, X7R, 0402; Manufacturer: MuRata; Polarized: N; CompType: Capacitor; Value: 0.015uF; U/M: EA; Cap_F: 0.000000015; Tolerance_%: 10; VDC_V: 16; Value2: 16V; TaMin_C: -55; TaMax_C: 125; Cap_Case: 0402; SizeArea_mm2: 0.5; SizeAreaWB_mm2: 3; SizeX_mm: 1; SizeZ_mm: 0.6; AEC Category: Q200; Green_Lifecycle: Active; Green_REACh: Passed
signal-integrity model Cap
simulation model Cap
footprint 0402
footprint 0402M
footprint 0402L
footprint 0402S
pins: 1, 2

## GRM155R71C154KA12D
designator C?  ValueDisplayed: 0.15µF  (hidden comment: GRM155R71C154KA12D)
CAP, CERM, 0.15 µF, 16 V,+/- 10%, X7R, 0402; Manufacturer: MuRata; Polarized: N; CompType: Capacitor; Value: 0.15uF; U/M: EA; Cap_F: 0.00000015; Tolerance_%: 10; VDC_V: 16; Value2: 16V; TaMin_C: -55; TaMax_C: 125; Cap_Case: 0402; SizeArea_mm2: 0.5; SizeAreaWB_mm2: 3; SizeX_mm: 1; SizeZ_mm: 0.6; AEC Category: Q200
signal-integrity model Cap
simulation model Cap
footprint 0402
footprint 0402M
footprint 0402L
footprint 0402S
pins: 1, 2

## GRM155R71C183KA01D
designator C?  ValueDisplayed: 0.018µF  (hidden comment: GRM155R71C183KA01D)
CAP, CERM, 0.018 µF, 16 V,+/- 10%, X7R, 0402; Manufacturer: MuRata; Polarized: N; CompType: Capacitor; Value: 0.018uF; U/M: EA; Cap_F: 0.000000018; Tolerance_%: 10; VDC_V: 16; Value2: 16V; TaMin_C: -55; TaMax_C: 125; Cap_Case: 0402; SizeArea_mm2: 0.5; SizeAreaWB_mm2: 3; SizeX_mm: 1; SizeZ_mm: 0.6; AEC Category: Q200
signal-integrity model Cap
simulation model Cap
footprint 0402
footprint 0402M
footprint 0402L
footprint 0402S
pins: 1, 2

## GRM155R71C222KA01D
designator C?  ValueDisplayed: 2200pF  (hidden comment: GRM155R71C222KA01D)
CAP, CERM, 2200 pF, 16 V,+/- 10%, X7R, 0402; Manufacturer: MuRata; Polarized: N; CompType: Capacitor; Value: 2200pF; U/M: EA; Cap_F: 0.0000000022; Tolerance_%: 10; VDC_V: 16; Value2: 16V; TaMin_C: -55; TaMax_C: 125; Cap_Case: 0402; SizeArea_mm2: 0.5; SizeAreaWB_mm2: 3; SizeX_mm: 1; SizeZ_mm: 0.6; AEC Category: Q200; Green_Lifecycle: Active; Green_REACh: Passed
signal-integrity model Cap
simulation model Cap
footprint 0402
footprint 0402M
footprint 0402L
footprint 0402S
pins: 1, 2

## GRM155R71C223KA01D
designator C?  ValueDisplayed: 0.022µF  (hidden comment: GRM155R71C223KA01D)
CAP, CERM, 0.022 µF, 16 V,+/- 10%, X7R, 0402; Manufacturer: MuRata; Polarized: N; CompType: Capacitor; Value: 0.022uF; U/M: EA; Cap_F: 0.000000022; Tolerance_%: 10; VDC_V: 16; Value2: 16V; TaMin_C: -55; TaMax_C: 125; Cap_Case: 0402; SizeArea_mm2: 0.5; SizeAreaWB_mm2: 3; SizeX_mm: 1; SizeZ_mm: 0.6; AEC Category: Q200; Green_Lifecycle: Active; Green_REACh: Passed
signal-integrity model Cap
simulation model Cap
footprint 0402
footprint 0402M
footprint 0402L
footprint 0402S
pins: 1, 2

## GRM155R71C224KA12D
designator C?  ValueDisplayed: 0.22µF  (hidden comment: GRM155R71C224KA12D)
CAP, CERM, 0.22 µF, 16 V,+/- 10%, X7R, 0402; Manufacturer: MuRata; Polarized: N; CompType: Capacitor; Value: 0.22uF; U/M: EA; Cap_F: 0.00000022; Tolerance_%: 10; VDC_V: 16; Value2: 16V; TaMin_C: -55; TaMax_C: 125; Cap_Case: 0402; SizeArea_mm2: 0.5; SizeAreaWB_mm2: 3; SizeX_mm: 1; SizeZ_mm: 0.6; AEC Category: Q200; Green_Lifecycle: Active; Green_REACh: Passed
signal-integrity model Cap
simulation model Cap
footprint 0402
footprint 0402M
footprint 0402L
footprint 0402S
pins: 1, 2

## GRM155R71C273KA01D
designator C?  ValueDisplayed: 0.027µF  (hidden comment: GRM155R71C273KA01D)
CAP, CERM, 0.027 µF, 16 V,+/- 10%, X7R, 0402; Manufacturer: MuRata; Polarized: N; CompType: Capacitor; Value: 0.027uF; U/M: EA; Cap_F: 0.000000027; Tolerance_%: 10; VDC_V: 16; Value2: 16V; TaMin_C: -55; TaMax_C: 125; Cap_Case: 0402; SizeArea_mm2: 0.5; SizeAreaWB_mm2: 3; SizeX_mm: 1; SizeZ_mm: 0.6; AEC Category: Q200
signal-integrity model Cap
simulation model Cap
footprint 0402
footprint 0402M
footprint 0402L
footprint 0402S
pins: 1, 2

## GRM155R71C333KA01D
designator C?  ValueDisplayed: 0.033µF  (hidden comment: GRM155R71C333KA01D)
CAP, CERM, 0.033 µF, 16 V,+/- 10%, X7R, 0402; Manufacturer: MuRata; Polarized: N; CompType: Capacitor; Value: 0.033uF; U/M: EA; Cap_F: 0.000000033; Tolerance_%: 10; VDC_V: 16; Value2: 16V; TaMin_C: -55; TaMax_C: 125; Cap_Case: 0402; SizeArea_mm2: 0.5; SizeAreaWB_mm2: 3; SizeX_mm: 1; SizeZ_mm: 0.6; AEC Category: Q200
signal-integrity model Cap
simulation model Cap
footprint 0402
footprint 0402M
footprint 0402L
footprint 0402S
pins: 1, 2

## GRM155R71C393KA01D
designator C?  ValueDisplayed: 0.039µF  (hidden comment: GRM155R71C393KA01D)
CAP, CERM, 0.039 µF, 16 V,+/- 10%, X7R, 0402; Manufacturer: MuRata; Polarized: N; CompType: Capacitor; Value: 0.039uF; U/M: EA; Cap_F: 0.000000039; Tolerance_%: 10; VDC_V: 16; Value2: 16V; TaMin_C: -55; TaMax_C: 125; Cap_Case: 0402; SizeArea_mm2: 0.5; SizeAreaWB_mm2: 3; SizeX_mm: 1; SizeZ_mm: 0.6; AEC Category: Q200
signal-integrity model Cap
simulation model Cap
footprint 0402
footprint 0402M
footprint 0402L
footprint 0402S
pins: 1, 2

## GRM155R71C472KA01D
designator C?  ValueDisplayed: 4700pF  (hidden comment: GRM155R71C472KA01D)
CAP, CERM, 4700 pF, 16 V,+/- 10%, X7R, 0402; Manufacturer: MuRata; Polarized: N; CompType: Capacitor; Value: 4700pF; U/M: EA; Cap_F: 0.0000000047; Tolerance_%: 10; VDC_V: 16; Value2: 16V; TaMin_C: -55; TaMax_C: 125; Cap_Case: 0402; SizeArea_mm2: 0.5; SizeAreaWB_mm2: 3; SizeX_mm: 1; SizeZ_mm: 0.6; AEC Category: Q200; Green_Lifecycle: Active; Green_REACh: Passed
signal-integrity model Cap
simulation model Cap
footprint 0402
footprint 0402M
footprint 0402L
footprint 0402S
pins: 1, 2

## GRM155R71C473KA01D
designator C?  ValueDisplayed: 0.047µF  (hidden comment: GRM155R71C473KA01D)
CAP, CERM, 0.047 µF, 16 V,+/- 10%, X7R, 0402; Manufacturer: MuRata; Polarized: N; CompType: Capacitor; Value: 0.047uF; U/M: EA; Cap_F: 0.000000047; Tolerance_%: 10; VDC_V: 16; Value2: 16V; TaMin_C: -55; TaMax_C: 125; Cap_Case: 0402; SizeArea_mm2: 0.5; SizeAreaWB_mm2: 3; SizeX_mm: 1; SizeZ_mm: 0.6; AEC Category: Q200; Green_Lifecycle: Active; Green_REACh: Passed
signal-integrity model Cap
simulation model Cap
footprint 0402
footprint 0402M
footprint 0402L
footprint 0402S
pins: 1, 2

## GRM155R71C563KA88D
designator C?  ValueDisplayed: 0.056µF  (hidden comment: GRM155R71C563KA88D)
CAP, CERM, 0.056 µF, 16 V,+/- 10%, X7R, 0402; Manufacturer: MuRata; Polarized: N; CompType: Capacitor; Value: 0.056uF; U/M: EA; Cap_F: 0.000000056; Tolerance_%: 10; VDC_V: 16; Value2: 16V; TaMin_C: -55; TaMax_C: 125; Cap_Case: 0402; SizeArea_mm2: 0.5; SizeAreaWB_mm2: 3; SizeX_mm: 1; SizeZ_mm: 0.6; AEC Category: Q200
signal-integrity model Cap
simulation model Cap
footprint 0402
footprint 0402M
footprint 0402L
footprint 0402S
pins: 1, 2

## GRM155R71C683KA88D
designator C?  ValueDisplayed: 0.068µF  (hidden comment: GRM155R71C683KA88D)
CAP, CERM, 0.068 µF, 16 V,+/- 10%, X7R, 0402; Manufacturer: MuRata; Polarized: N; CompType: Capacitor; Value: 0.068uF; U/M: EA; Cap_F: 0.000000068; Tolerance_%: 10; VDC_V: 16; Value2: 16V; TaMin_C: -55; TaMax_C: 125; Cap_Case: 0402; SizeArea_mm2: 0.5; SizeAreaWB_mm2: 3; SizeX_mm: 1; SizeZ_mm: 0.6; AEC Category: Q200
signal-integrity model Cap
simulation model Cap
footprint 0402
footprint 0402M
footprint 0402L
footprint 0402S
pins: 1, 2

## GRM155R71C822KA01D
designator C?  ValueDisplayed: 8200pF  (hidden comment: GRM155R71C822KA01D)
CAP, CERM, 8200 pF, 16 V,+/- 10%, X7R, 0402; Manufacturer: MuRata; Polarized: N; CompType: Capacitor; Value: 8200pF; U/M: EA; Cap_F: 0.0000000082; Tolerance_%: 10; VDC_V: 16; Value2: 16V; TaMin_C: -55; TaMax_C: 125; Cap_Case: 0402; SizeArea_mm2: 0.5; SizeAreaWB_mm2: 3; SizeX_mm: 1; SizeZ_mm: 0.6; AEC Category: Q200; Green_Lifecycle: Active; Green_REACh: Passed
signal-integrity model Cap
simulation model Cap
footprint 0402
footprint 0402M
footprint 0402L
footprint 0402S
pins: 1, 2

## GRM155R71C823KA88D
designator C?  ValueDisplayed: 0.082µF  (hidden comment: GRM155R71C823KA88D)
CAP, CERM, 0.082 µF, 16 V,+/- 10%, X7R, 0402; Manufacturer: MuRata; Polarized: N; CompType: Capacitor; Value: 0.082uF; U/M: EA; Cap_F: 0.000000082; Tolerance_%: 10; VDC_V: 16; Value2: 16V; TaMin_C: -55; TaMax_C: 125; Cap_Case: 0402; SizeArea_mm2: 0.5; SizeAreaWB_mm2: 3; SizeX_mm: 1; SizeZ_mm: 0.6; AEC Category: Q200
signal-integrity model Cap
simulation model Cap
footprint 0402
footprint 0402M
footprint 0402L
footprint 0402S
pins: 1, 2

## GRM155R71E103KA01D
designator C?  ValueDisplayed: 0.01µF  (hidden comment: GRM155R71E103KA01D)
CAP, CERM, 0.01 µF, 25 V,+/- 10%, X7R, 0402; Manufacturer: MuRata; Polarized: N; CompType: Capacitor; Value: 0.01uF; U/M: EA; Cap_F: 0.00000001; Tolerance_%: 10; VDC_V: 25; Value2: 25V; TaMin_C: -55; TaMax_C: 125; Cap_Case: 0402; SizeArea_mm2: 0.5; SizeAreaWB_mm2: 3; SizeX_mm: 1; SizeZ_mm: 0.6; AEC Category: Q200; Green_Lifecycle: Active; Green_REACh: Passed
signal-integrity model Cap
simulation model Cap
footprint 0402
footprint 0402M
footprint 0402L
footprint 0402S
pins: 1, 2

## GRM155R71E104KE14D
designator C?  ValueDisplayed: 0.1µF  (hidden comment: GRM155R71E104KE14D)
CAP, CERM, 0.1 µF, 25 V,+/- 10%, X7R, 0402; Manufacturer: MuRata; Polarized: N; CompType: Capacitor; Value: 0.1uF; U/M: EA; Cap_F: 0.0000001; Tolerance_%: 10; VDC_V: 25; Value2: 25V; TaMin_C: -55; TaMax_C: 125; Cap_Case: 0402; SizeArea_mm2: 0.5; SizeAreaWB_mm2: 3; SizeX_mm: 1; SizeZ_mm: 0.6; AEC Category: Q200; Green_Lifecycle: Active; Green_REACh: Passed
signal-integrity model Cap
simulation model Cap
footprint 0402
footprint 0402M
footprint 0402L
footprint 0402S
pins: 1, 2

## GRM155R71E123KA61D
designator C?  ValueDisplayed: 0.012µF  (hidden comment: GRM155R71E123KA61D)
CAP, CERM, 0.012 µF, 25 V,+/- 10%, X7R, 0402; Manufacturer: MuRata; Polarized: N; CompType: Capacitor; Value: 0.012uF; U/M: EA; Cap_F: 0.000000012; Tolerance_%: 10; VDC_V: 25; Value2: 25V; TaMin_C: -55; TaMax_C: 125; Cap_Case: 0402; SizeArea_mm2: 0.5; SizeAreaWB_mm2: 3; SizeX_mm: 1; SizeZ_mm: 0.6; AEC Category: Q200
signal-integrity model Cap
simulation model Cap
footprint 0402
footprint 0402M
footprint 0402L
footprint 0402S
pins: 1, 2

## GRM155R71E153KA61D
designator C?  ValueDisplayed: 0.015µF  (hidden comment: GRM155R71E153KA61D)
CAP, CERM, 0.015 µF, 25 V,+/- 10%, X7R, 0402; Manufacturer: MuRata; Polarized: N; CompType: Capacitor; Value: 0.015uF; U/M: EA; Cap_F: 0.000000015; Tolerance_%: 10; VDC_V: 25; Value2: 25V; TaMin_C: -55; TaMax_C: 125; Cap_Case: 0402; SizeArea_mm2: 0.5; SizeAreaWB_mm2: 3; SizeX_mm: 1; SizeZ_mm: 0.6; AEC Category: Q200
signal-integrity model Cap
simulation model Cap
footprint 0402
footprint 0402M
footprint 0402L
footprint 0402S
pins: 1, 2

## GRM155R71E183KA61D
designator C?  ValueDisplayed: 0.018µF  (hidden comment: GRM155R71E183KA61D)
CAP, CERM, 0.018 µF, 25 V,+/- 10%, X7R, 0402; Manufacturer: MuRata; Polarized: N; CompType: Capacitor; Value: 0.018uF; U/M: EA; Cap_F: 0.000000018; Tolerance_%: 10; VDC_V: 25; Value2: 25V; TaMin_C: -55; TaMax_C: 125; Cap_Case: 0402; SizeArea_mm2: 0.5; SizeAreaWB_mm2: 3; SizeX_mm: 1; SizeZ_mm: 0.6; AEC Category: Q200
signal-integrity model Cap
simulation model Cap
footprint 0402
footprint 0402M
footprint 0402L
footprint 0402S
pins: 1, 2

## GRM155R71E222KA01D
designator C?  ValueDisplayed: 2200pF  (hidden comment: GRM155R71E222KA01D)
CAP, CERM, 2200 pF, 25 V,+/- 10%, X7R, 0402; Manufacturer: MuRata; Polarized: N; CompType: Capacitor; Value: 2200pF; U/M: EA; Cap_F: 0.0000000022; Tolerance_%: 10; VDC_V: 25; Value2: 25V; TaMin_C: -55; TaMax_C: 125; Cap_Case: 0402; SizeArea_mm2: 0.5; SizeAreaWB_mm2: 3; SizeX_mm: 1; SizeZ_mm: 0.6; AEC Category: Q200; Green_Lifecycle: Active; Green_REACh: Passed
signal-integrity model Cap
simulation model Cap
footprint 0402
footprint 0402M
footprint 0402L
footprint 0402S
pins: 1, 2

## GRM155R71E223KA61D
designator C?  ValueDisplayed: 0.022µF  (hidden comment: GRM155R71E223KA61D)
CAP, CERM, 0.022 µF, 25 V,+/- 10%, X7R, 0402; Manufacturer: MuRata; Polarized: N; CompType: Capacitor; Value: 0.022uF; U/M: EA; Cap_F: 0.000000022; Tolerance_%: 10; VDC_V: 25; Value2: 25V; TaMin_C: -55; TaMax_C: 125; Cap_Case: 0402; SizeArea_mm2: 0.5; SizeAreaWB_mm2: 3; SizeX_mm: 1; SizeZ_mm: 0.6; AEC Category: Q200; Green_Lifecycle: Active; Green_REACh: Passed
signal-integrity model Cap
simulation model Cap
footprint 0402
footprint 0402M
footprint 0402L
footprint 0402S
pins: 1, 2

## GRM155R71E273KA88D
designator C?  ValueDisplayed: 0.027µF  (hidden comment: GRM155R71E273KA88D)
CAP, CERM, 0.027 µF, 25 V,+/- 10%, X7R, 0402; Manufacturer: MuRata; Polarized: N; CompType: Capacitor; Value: 0.027uF; U/M: EA; Cap_F: 0.000000027; Tolerance_%: 10; VDC_V: 25; Value2: 25V; TaMin_C: -55; TaMax_C: 125; Cap_Case: 0402; SizeArea_mm2: 0.5; SizeAreaWB_mm2: 3; SizeX_mm: 1; SizeZ_mm: 0.6; AEC Category: Q200; Green_Lifecycle: Active; Green_REACh: Passed
signal-integrity model Cap
simulation model Cap
footprint 0402
footprint 0402M
footprint 0402L
footprint 0402S
pins: 1, 2

## GRM155R71E333KA88D
designator C?  ValueDisplayed: 0.033µF  (hidden comment: GRM155R71E333KA88D)
CAP, CERM, 0.033 µF, 25 V,+/- 10%, X7R, 0402; Manufacturer: MuRata; Polarized: N; CompType: Capacitor; Value: 0.033uF; U/M: EA; Cap_F: 0.000000033; Tolerance_%: 10; VDC_V: 25; Value2: 25V; TaMin_C: -55; TaMax_C: 125; Cap_Case: 0402; SizeArea_mm2: 0.5; SizeAreaWB_mm2: 3; SizeX_mm: 1; SizeZ_mm: 0.6; AEC Category: Q200; Green_Lifecycle: Active; Green_REACh: Passed
signal-integrity model Cap
simulation model Cap
footprint 0402
footprint 0402M
footprint 0402L
footprint 0402S
pins: 1, 2

## GRM155R71E393KA88D
designator C?  ValueDisplayed: 0.039µF  (hidden comment: GRM155R71E393KA88D)
CAP, CERM, 0.039 µF, 25 V,+/- 10%, X7R, 0402; Manufacturer: MuRata; Polarized: N; CompType: Capacitor; Value: 0.039uF; U/M: EA; Cap_F: 0.000000039; Tolerance_%: 10; VDC_V: 25; Value2: 25V; TaMin_C: -55; TaMax_C: 125; Cap_Case: 0402; SizeArea_mm2: 0.5; SizeAreaWB_mm2: 3; SizeX_mm: 1; SizeZ_mm: 0.6; AEC Category: Q200
signal-integrity model Cap
simulation model Cap
footprint 0402
footprint 0402M
footprint 0402L
footprint 0402S
pins: 1, 2

## GRM155R71E472KA01D
designator C?  ValueDisplayed: 4700pF  (hidden comment: GRM155R71E472KA01D)
CAP, CERM, 4700 pF, 25 V,+/- 10%, X7R, 0402; Manufacturer: MuRata; Polarized: N; CompType: Capacitor; Value: 4700pF; U/M: EA; Cap_F: 0.0000000047; Tolerance_%: 10; VDC_V: 25; Value2: 25V; TaMin_C: -55; TaMax_C: 125; Cap_Case: 0402; SizeArea_mm2: 0.5; SizeAreaWB_mm2: 3; SizeX_mm: 1; SizeZ_mm: 0.6; AEC Category: Q200; Green_Lifecycle: Active; Green_REACh: Passed
signal-integrity model Cap
simulation model Cap
footprint 0402
footprint 0402M
footprint 0402L
footprint 0402S
pins: 1, 2

## GRM155R71E473KA88D
designator C?  ValueDisplayed: 0.047µF  (hidden comment: GRM155R71E473KA88D)
CAP, CERM, 0.047 µF, 25 V,+/- 10%, X7R, 0402; Manufacturer: MuRata; Polarized: N; CompType: Capacitor; Value: 0.047uF; U/M: EA; Cap_F: 0.000000047; Tolerance_%: 10; VDC_V: 25; Value2: 25V; TaMin_C: -55; TaMax_C: 125; Cap_Case: 0402; SizeArea_mm2: 0.5; SizeAreaWB_mm2: 3; SizeX_mm: 1; SizeZ_mm: 0.6; AEC Category: Q200; Green_Lifecycle: Active; Green_REACh: Passed
signal-integrity model Cap
simulation model Cap
footprint 0402
footprint 0402M
footprint 0402L
footprint 0402S
pins: 1, 2

## GRM155R71E562KA01D
designator C?  ValueDisplayed: 5600pF  (hidden comment: GRM155R71E562KA01D)
CAP, CERM, 5600 pF, 25 V,+/- 10%, X7R, 0402; Manufacturer: MuRata; Polarized: N; CompType: Capacitor; Value: 5600pF; U/M: EA; Cap_F: 0.0000000056; Tolerance_%: 10; VDC_V: 25; Value2: 25V; TaMin_C: -55; TaMax_C: 125; Cap_Case: 0402; SizeArea_mm2: 0.5; SizeAreaWB_mm2: 3; SizeX_mm: 1; SizeZ_mm: 0.6; AEC Category: Q200
signal-integrity model Cap
simulation model Cap
footprint 0402
footprint 0402M
footprint 0402L
footprint 0402S
pins: 1, 2

## GRM155R71E682KA01D
designator C?  ValueDisplayed: 6800pF  (hidden comment: GRM155R71E682KA01D)
CAP, CERM, 6800 pF, 25 V,+/- 10%, X7R, 0402; Manufacturer: MuRata; Polarized: N; CompType: Capacitor; Value: 6800pF; U/M: EA; Cap_F: 0.0000000068; Tolerance_%: 10; VDC_V: 25; Value2: 25V; TaMin_C: -55; TaMax_C: 125; Cap_Case: 0402; SizeArea_mm2: 0.5; SizeAreaWB_mm2: 3; SizeX_mm: 1; SizeZ_mm: 0.6; AEC Category: Q200; Green_Lifecycle: Active; Green_REACh: Passed
signal-integrity model Cap
simulation model Cap
footprint 0402
footprint 0402M
footprint 0402L
footprint 0402S
pins: 1, 2

## GRM155R71E822KA01D
designator C?  ValueDisplayed: 8200pF  (hidden comment: GRM155R71E822KA01D)
CAP, CERM, 8200 pF, 25 V,+/- 10%, X7R, 0402; Manufacturer: MuRata; Polarized: N; CompType: Capacitor; Value: 8200pF; U/M: EA; Cap_F: 0.0000000082; Tolerance_%: 10; VDC_V: 25; Value2: 25V; TaMin_C: -55; TaMax_C: 125; Cap_Case: 0402; SizeArea_mm2: 0.5; SizeAreaWB_mm2: 3; SizeX_mm: 1; SizeZ_mm: 0.6; AEC Category: Q200
signal-integrity model Cap
simulation model Cap
footprint 0402
footprint 0402M
footprint 0402L
footprint 0402S
pins: 1, 2

## GRM155R71H102KA01D
designator C?  ValueDisplayed: 1000pF  (hidden comment: GRM155R71H102KA01D)
CAP, CERM, 1000 pF, 50 V,+/- 10%, X7R, 0402; Manufacturer: MuRata; Polarized: N; CompType: Capacitor; Value: 1000pF; U/M: EA; Cap_F: 0.000000001; Tolerance_%: 10; VDC_V: 50; Value2: 50V; TaMin_C: -55; TaMax_C: 125; Cap_Case: 0402; SizeArea_mm2: 0.5; SizeAreaWB_mm2: 3; SizeX_mm: 1; SizeZ_mm: 0.6; AEC Category: Q200; Green_Lifecycle: Active; Green_REACh: Passed
signal-integrity model Cap
simulation model Cap
footprint 0402
footprint 0402M
footprint 0402L
footprint 0402S
pins: 1, 2

## GRM155R71H103KA88D
designator C?  ValueDisplayed: 0.01µF  (hidden comment: GRM155R71H103KA88D)
CAP, CERM, 0.01 µF, 50 V,+/- 10%, X7R, 0402; Manufacturer: MuRata; Polarized: N; CompType: Capacitor; Value: 0.01uF; U/M: EA; Cap_F: 0.00000001; Tolerance_%: 10; VDC_V: 50; Value2: 50V; TaMin_C: -55; TaMax_C: 125; Cap_Case: 0402; SizeArea_mm2: 0.5; SizeAreaWB_mm2: 3; SizeX_mm: 1; SizeZ_mm: 0.6; AEC Category: Q200; Green_Lifecycle: Active; Green_REACh: Passed
signal-integrity model Cap
simulation model Cap
footprint 0402
footprint 0402M
footprint 0402L
footprint 0402S
pins: 1, 2

## GRM155R71H104ME14D
designator C?  ValueDisplayed: 0.1µF  (hidden comment: GRM155R71H104ME14D)
CAP, CERM, 0.1 µF, 50 V,+/- 20%, X7R, 0402; Manufacturer: MuRata; Polarized: N; CompType: Capacitor; Value: 0.1uF; U/M: EA; Cap_F: 0.0000001; Tolerance_%: 20; VDC_V: 50; Value2: 50V; TaMin_C: -55; TaMax_C: 125; Cap_Case: 0402; SizeArea_mm2: 0.5; SizeAreaWB_mm2: 3; SizeX_mm: 1; SizeZ_mm: 0.6; AEC Category: Q200
signal-integrity model Cap
simulation model Cap
footprint 0402
footprint 0402M
footprint 0402L
footprint 0402S
pins: 1, 2

## GRM155R71H122KA01D
designator C?  ValueDisplayed: 1200pF  (hidden comment: GRM155R71H122KA01D)
CAP, CERM, 1200 pF, 50 V,+/- 10%, X7R, 0402; Manufacturer: MuRata; Polarized: N; CompType: Capacitor; Value: 1200pF; U/M: EA; Cap_F: 0.0000000012; Tolerance_%: 10; VDC_V: 50; Value2: 50V; TaMin_C: -55; TaMax_C: 125; Cap_Case: 0402; SizeArea_mm2: 0.5; SizeAreaWB_mm2: 3; SizeX_mm: 1; SizeZ_mm: 0.6; AEC Category: Q200
signal-integrity model Cap
simulation model Cap
footprint 0402
footprint 0402M
footprint 0402L
footprint 0402S
pins: 1, 2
